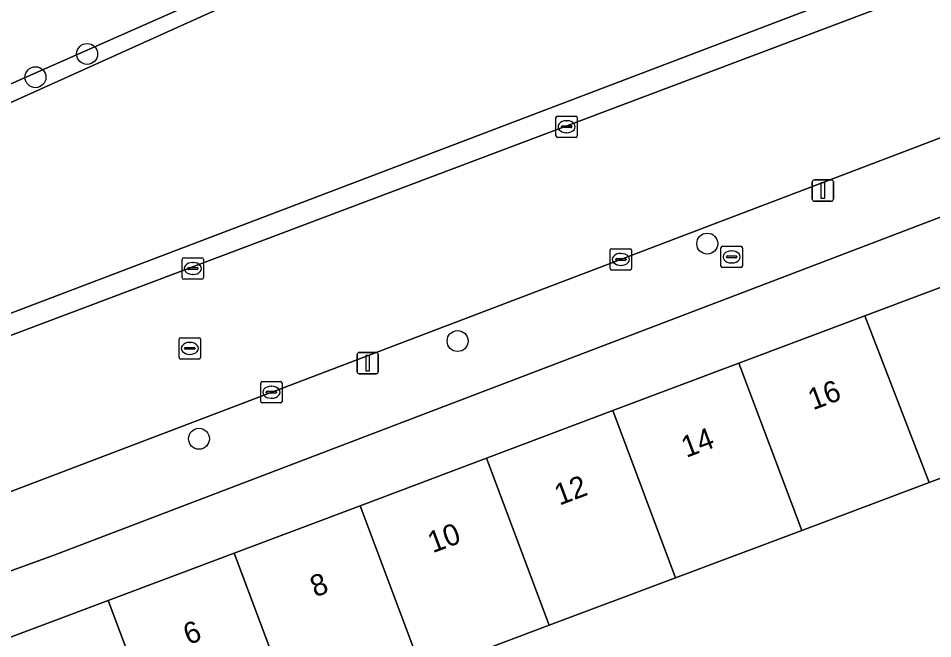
# Model space of a CAD drawing. Extents: x 161248 to 161848, y 384871 to 385383.
# Drawn here: x 161537.26 to 161580.03, y 385046.89 to 385075.88 of the extents above; entities that cross this region are included whole.
import ezdxf

# ---------------------------------------------------------------- set-up
doc = ezdxf.new("R2010")
doc.units = 0
for name, color, linetype in [('IMGEO_Boom', 7, 'Continuous'), ('IMGEO_Brandkraan', 7, 'Continuous'), ('IMGEO_Erf', 7, 'Continuous'), ('IMGEO_Groenvoorziening', 7, 'Continuous'), ('IMGEO_Kolk', 7, 'Continuous'), ('IMGEO_Lichtmast', 7, 'Continuous'), ('IMGEO_Pand', 7, 'Continuous'), ('IMGEO_Pand_nummerreeks', 7, 'Continuous'), ('IMGEO_Rijbaan_lokaal_open', 7, 'Continuous'), ('IMGEO_Rioolput', 7, 'Continuous'), ('IMGEO_Voetpad_halfverhard', 7, 'Continuous'), ('IMGEO_Voetpad_open', 7, 'Continuous')]:
    doc.layers.add(name, color=color, linetype=linetype)

msp = doc.modelspace()

# ---------------------------------------------------------------- linework, layer by layer
at = {"layer": 'IMGEO_Boom'}
for centre in [(161540.479, 385074.214), (161538.063, 385073.126), (161569.486, 385065.35), (161557.809, 385060.797), (161545.712, 385056.231)]:
    msp.add_circle(centre, 0.489, dxfattribs=at)
at = {"layer": 'IMGEO_Brandkraan'}
for p, q in [((161570.125, 385064.303), (161570.125, 385065.155)), ((161570.2, 385065.229), (161571.052, 385065.229)), ((161570.613, 385065.009), (161570.638, 385065.009)), ((161571.126, 385065.155), (161571.126, 385064.303)), ((161570.384, 385064.723), (161570.384, 385064.735)), ((161570.822, 385064.686), (161570.424, 385064.686)), ((161570.427, 385064.772), (161570.825, 385064.772)), ((161570.868, 385064.735), (161570.868, 385064.723)), ((161571.052, 385064.229), (161570.2, 385064.229)), ((161570.636, 385064.449), (161570.611, 385064.449))]:
    msp.add_line(p, q, dxfattribs=at)
for points in [[(161570.125, 385064.303), (161570.125, 385065.155)], [(161570.2, 385065.229), (161571.052, 385065.229)], [(161571.126, 385065.155), (161571.126, 385064.303)], [(161571.052, 385064.229), (161570.2, 385064.229)]]:
    msp.add_lwpolyline(points, dxfattribs=at)
for centre, radius, start, end in [((161570.202, 385065.153), 0.0765, 91.552, 178.448), ((161570.202, 385065.153), 0.0765, 91.552, 178.448), ((161571.05, 385065.153), 0.0765, 1.552, 88.448), ((161571.05, 385065.153), 0.0765, 1.552, 88.448), ((161570.424, 385064.732), 0.0403, 85.8775, 175.7526), ((161570.421, 385064.722), 0.0366, 178.938, 274.7102), ((161570.825, 385064.729), 0.043, 264.8664, 352.4533), ((161570.829, 385064.734), 0.0386, 1.7309, 96.639), ((161570.202, 385064.305), 0.0765, 181.552, 268.448), ((161570.202, 385064.305), 0.0765, 181.552, 268.448), ((161571.05, 385064.305), 0.0765, 271.552, 358.448), ((161571.05, 385064.305), 0.0765, 271.552, 358.448)]:
    msp.add_arc(centre, radius, start, end, dxfattribs=at)
for centre, major_axis, ratio, start_param, end_param in [((161570.612, 385064.729), (-0.387, 0.002), 0.722429, 4.712389, 7.853982), ((161570.637, 385064.729), (-0.39, 0.002), 0.717154, 1.570796, 4.712389)]:
    msp.add_ellipse(centre, major_axis=major_axis, ratio=ratio, start_param=start_param, end_param=end_param, dxfattribs=at)
at = {"layer": 'IMGEO_Erf'}
msp.add_lwpolyline([(161565.073, 385057.547), (161570.967, 385059.761), (161576.862, 385061.975), (161582.755, 385064.189), (161588.79, 385066.456), (161589.145, 385065.512), (161592.95, 385067.024), (161591.594, 385070.858), (161538.894, 385050.769), (161528.473, 385047.01), (161529.493, 385044.181), (161535.556, 385046.459), (161541.46, 385048.676), (161547.354, 385050.891), (161553.247, 385053.104), (161559.16, 385055.326)], close=True, dxfattribs=at)
msp.add_lwpolyline([(161584.899, 385044.98), (161583.845, 385047.786), (161588.289, 385049.455), (161592.924, 385051.196), (161593.978, 385048.391), (161594.068, 385048.384), (161594.788, 385056.581), (161592.778, 385055.838), (161592.992, 385055.269), (161586.963, 385053.005), (161585.689, 385056.378), (161579.872, 385054.193), (161573.901, 385051.95), (161568.007, 385049.736), (161562.095, 385047.515), (161556.182, 385045.294)], dxfattribs=at)
at = {"layer": 'IMGEO_Groenvoorziening'}
msp.add_lwpolyline([(161546.898, 385076.445), (161555.221, 385080.061), (161576.826, 385088.455), (161578.405, 385089.13), (161583.611, 385090.971), (161582.461, 385092.975), (161582.198, 385092.828), (161581.929, 385092.695), (161530.726, 385070.086), (161528.198, 385068.97), (161526.333, 385068.119), (161519.737, 385065.162), (161517.388, 385070.417), (161517.114, 385071.036), (161516.497, 385070.729), (161518.098, 385067.11), (161519.266, 385064.472), (161519.439, 385064.08)], close=True, dxfattribs=at)
msp.add_lwpolyline([(161589.28, 385082.44), (161583.611, 385090.971), (161578.405, 385089.13), (161576.826, 385088.455), (161555.221, 385080.061), (161546.898, 385076.445), (161519.439, 385064.08), (161519.074, 385063.916), (161512.396, 385060.909), (161515.187, 385054.666), (161520.946, 385056.425), (161531.74, 385060.145), (161584.888, 385080.338)], dxfattribs=at)
at = {"layer": 'IMGEO_Kolk'}
for p, q in [((161562.405, 385070.387), (161562.405, 385071.239)), ((161562.48, 385071.313), (161563.332, 385071.313)), ((161562.893, 385071.093), (161562.918, 385071.093)), ((161563.406, 385071.239), (161563.406, 385070.387)), ((161562.664, 385070.807), (161562.664, 385070.819)), ((161563.102, 385070.77), (161562.704, 385070.77)), ((161562.707, 385070.856), (161563.105, 385070.856)), ((161562.916, 385070.533), (161562.891, 385070.533)), ((161563.148, 385070.819), (161563.148, 385070.807)), ((161563.332, 385070.313), (161562.48, 385070.313)), ((161564.944, 385064.185), (161564.944, 385065.037)), ((161565.019, 385065.111), (161565.871, 385065.111)), ((161565.945, 385065.037), (161565.945, 385064.185)), ((161544.924, 385063.762), (161544.924, 385064.614)), ((161544.999, 385064.688), (161545.851, 385064.688)), ((161545.925, 385064.614), (161545.925, 385063.762)), ((161565.203, 385064.605), (161565.203, 385064.617)), ((161565.641, 385064.568), (161565.243, 385064.568)), ((161565.246, 385064.654), (161565.644, 385064.654)), ((161565.432, 385064.891), (161565.457, 385064.891)), ((161565.687, 385064.617), (161565.687, 385064.605)), ((161545.183, 385064.182), (161545.183, 385064.194)), ((161545.621, 385064.145), (161545.223, 385064.145)), ((161545.226, 385064.231), (161545.624, 385064.231)), ((161545.412, 385064.468), (161545.437, 385064.468)), ((161545.667, 385064.194), (161545.667, 385064.182)), ((161565.871, 385064.111), (161565.019, 385064.111)), ((161565.455, 385064.331), (161565.43, 385064.331)), ((161545.851, 385063.688), (161544.999, 385063.688)), ((161545.435, 385063.908), (161545.41, 385063.908)), ((161548.6, 385057.979), (161548.6, 385058.831)), ((161548.675, 385058.905), (161549.527, 385058.905)), ((161549.088, 385058.685), (161549.113, 385058.685)), ((161549.601, 385058.831), (161549.601, 385057.979)), ((161548.859, 385058.399), (161548.859, 385058.411)), ((161549.297, 385058.362), (161548.899, 385058.362)), ((161548.902, 385058.448), (161549.3, 385058.448)), ((161549.111, 385058.125), (161549.086, 385058.125)), ((161549.343, 385058.411), (161549.343, 385058.399)), ((161549.527, 385057.905), (161548.675, 385057.905))]:
    msp.add_line(p, q, dxfattribs=at)
for points in [[(161562.405, 385070.387), (161562.405, 385071.239)], [(161562.48, 385071.313), (161563.332, 385071.313)], [(161563.406, 385071.239), (161563.406, 385070.387)], [(161563.332, 385070.313), (161562.48, 385070.313)], [(161564.944, 385064.185), (161564.944, 385065.037)], [(161565.019, 385065.111), (161565.871, 385065.111)], [(161565.945, 385065.037), (161565.945, 385064.185)], [(161544.924, 385063.762), (161544.924, 385064.614)], [(161544.999, 385064.688), (161545.851, 385064.688)], [(161545.925, 385064.614), (161545.925, 385063.762)], [(161565.871, 385064.111), (161565.019, 385064.111)], [(161545.851, 385063.688), (161544.999, 385063.688)], [(161548.6, 385057.979), (161548.6, 385058.831)], [(161548.675, 385058.905), (161549.527, 385058.905)], [(161549.601, 385058.831), (161549.601, 385057.979)], [(161549.527, 385057.905), (161548.675, 385057.905)]]:
    msp.add_lwpolyline(points, dxfattribs=at)
for centre, radius, start, end in [((161562.482, 385071.237), 0.0765, 91.552, 178.448), ((161562.482, 385071.237), 0.0765, 91.552, 178.448), ((161563.33, 385071.237), 0.0765, 1.552, 88.448), ((161563.33, 385071.237), 0.0765, 1.552, 88.448), ((161562.704, 385070.816), 0.0403, 85.8775, 175.7526), ((161562.701, 385070.806), 0.0366, 178.938, 274.7102), ((161563.105, 385070.813), 0.043, 264.8664, 352.4533), ((161563.109, 385070.818), 0.0386, 1.7309, 96.639), ((161562.482, 385070.389), 0.0765, 181.552, 268.448), ((161562.482, 385070.389), 0.0765, 181.552, 268.448), ((161563.33, 385070.389), 0.0765, 271.552, 358.448), ((161563.33, 385070.389), 0.0765, 271.552, 358.448), ((161565.021, 385065.035), 0.0765, 91.552, 178.448), ((161565.021, 385065.035), 0.0765, 91.552, 178.448), ((161565.869, 385065.035), 0.0765, 1.552, 88.448), ((161565.869, 385065.035), 0.0765, 1.552, 88.448), ((161545.001, 385064.612), 0.0765, 91.552, 178.448), ((161545.001, 385064.612), 0.0765, 91.552, 178.448), ((161545.849, 385064.612), 0.0765, 1.552, 88.448), ((161545.849, 385064.612), 0.0765, 1.552, 88.448), ((161565.243, 385064.614), 0.0403, 85.8775, 175.7526), ((161565.24, 385064.604), 0.0366, 178.938, 274.7102), ((161565.644, 385064.611), 0.043, 264.8664, 352.4533), ((161565.648, 385064.616), 0.0386, 1.7309, 96.639), ((161545.223, 385064.191), 0.0403, 85.8775, 175.7526), ((161545.22, 385064.181), 0.0366, 178.938, 274.7102), ((161545.624, 385064.188), 0.043, 264.8664, 352.4533), ((161545.628, 385064.193), 0.0386, 1.7309, 96.639), ((161565.021, 385064.187), 0.0765, 181.552, 268.448), ((161565.021, 385064.187), 0.0765, 181.552, 268.448), ((161565.869, 385064.187), 0.0765, 271.552, 358.448), ((161565.869, 385064.187), 0.0765, 271.552, 358.448), ((161545.001, 385063.764), 0.0765, 181.552, 268.448), ((161545.001, 385063.764), 0.0765, 181.552, 268.448), ((161545.849, 385063.764), 0.0765, 271.552, 358.448), ((161545.849, 385063.764), 0.0765, 271.552, 358.448), ((161548.677, 385058.829), 0.0765, 91.552, 178.448), ((161548.677, 385058.829), 0.0765, 91.552, 178.448), ((161549.525, 385058.829), 0.0765, 1.552, 88.448), ((161549.525, 385058.829), 0.0765, 1.552, 88.448), ((161548.899, 385058.408), 0.0403, 85.8775, 175.7526), ((161548.896, 385058.398), 0.0366, 178.938, 274.7102), ((161549.3, 385058.405), 0.043, 264.8664, 352.4533), ((161549.304, 385058.41), 0.0386, 1.7309, 96.639), ((161548.677, 385057.981), 0.0765, 181.552, 268.448), ((161548.677, 385057.981), 0.0765, 181.552, 268.448), ((161549.525, 385057.981), 0.0765, 271.552, 358.448), ((161549.525, 385057.981), 0.0765, 271.552, 358.448)]:
    msp.add_arc(centre, radius, start, end, dxfattribs=at)
for centre, major_axis, ratio, start_param, end_param in [((161562.892, 385070.813), (-0.387, 0.002), 0.722429, 4.712389, 7.853982), ((161562.917, 385070.813), (-0.39, 0.002), 0.717154, 1.570796, 4.712389), ((161565.431, 385064.611), (-0.387, 0.002), 0.722429, 4.712389, 7.853982), ((161565.456, 385064.611), (-0.39, 0.002), 0.717154, 1.570796, 4.712389), ((161545.411, 385064.188), (-0.387, 0.002), 0.722429, 4.712389, 7.853982), ((161545.436, 385064.188), (-0.39, 0.002), 0.717154, 1.570796, 4.712389), ((161549.087, 385058.405), (-0.387, 0.002), 0.722429, 4.712389, 7.853982), ((161549.112, 385058.405), (-0.39, 0.002), 0.717154, 1.570796, 4.712389)]:
    msp.add_ellipse(centre, major_axis=major_axis, ratio=ratio, start_param=start_param, end_param=end_param, dxfattribs=at)
at = {"layer": 'IMGEO_Lichtmast'}
for p, q in [((161574.495, 385068.33), (161575.285, 385068.33)), ((161575.285, 385068.33), (161574.495, 385068.33)), ((161574.395, 385067.43), (161574.395, 385068.23)), ((161574.395, 385068.23), (161574.395, 385067.43)), ((161575.385, 385068.23), (161575.385, 385067.43)), ((161575.385, 385067.43), (161575.385, 385068.23)), ((161575.285, 385067.33), (161574.495, 385067.33)), ((161574.495, 385067.33), (161575.285, 385067.33)), ((161553.208, 385060.266), (161553.998, 385060.266)), ((161553.998, 385060.266), (161553.208, 385060.266)), ((161553.108, 385059.366), (161553.108, 385060.166)), ((161553.108, 385060.166), (161553.108, 385059.366)), ((161554.098, 385060.166), (161554.098, 385059.366)), ((161554.098, 385059.366), (161554.098, 385060.166)), ((161553.998, 385059.266), (161553.208, 385059.266)), ((161553.208, 385059.266), (161553.998, 385059.266))]:
    msp.add_line(p, q, dxfattribs=at)
for points in [[(161574.815, 385068.205), (161574.965, 385068.205), (161574.965, 385067.455), (161574.815, 385067.455), (161574.815, 385068.205)], [(161553.528, 385060.141), (161553.678, 385060.141), (161553.678, 385059.391), (161553.528, 385059.391), (161553.528, 385060.141)]]:
    msp.add_lwpolyline(points, dxfattribs=at)
for centre, start, end in [((161574.495, 385068.23), 90, 180), ((161574.495, 385068.23), 90, 180), ((161575.285, 385068.23), 0, 90), ((161575.285, 385068.23), 360, 90), ((161574.495, 385067.43), 180, 270), ((161574.495, 385067.43), 180, 270), ((161575.285, 385067.43), 270, 0), ((161575.285, 385067.43), 270, 0), ((161553.208, 385060.166), 90, 180), ((161553.208, 385060.166), 90, 180), ((161553.998, 385060.166), 0, 90), ((161553.998, 385060.166), 360, 90), ((161553.208, 385059.366), 180, 270), ((161553.208, 385059.366), 180, 270), ((161553.998, 385059.366), 270, 0), ((161553.998, 385059.366), 270, 0)]:
    msp.add_arc(centre, 0.1, start, end, dxfattribs=at)
at = {"layer": 'IMGEO_Pand'}
for points in [[(161582.755, 385064.189), (161576.862, 385061.975), (161579.872, 385054.193), (161585.689, 385056.378)], [(161573.901, 385051.95), (161579.872, 385054.193), (161576.862, 385061.975), (161570.967, 385059.761)], [(161568.007, 385049.736), (161573.901, 385051.95), (161570.967, 385059.761), (161565.073, 385057.547)], [(161565.073, 385057.547), (161559.16, 385055.326), (161562.095, 385047.515), (161568.007, 385049.736)], [(161559.16, 385055.326), (161553.247, 385053.104), (161556.182, 385045.294), (161562.095, 385047.515)], [(161550.288, 385043.079), (161556.182, 385045.294), (161553.247, 385053.104), (161547.354, 385050.891)], [(161544.394, 385040.865), (161550.288, 385043.079), (161547.354, 385050.891), (161541.46, 385048.676)], [(161541.46, 385048.676), (161535.556, 385046.459), (161538.491, 385038.648), (161544.394, 385040.865)]]:
    msp.add_lwpolyline(points, close=True, dxfattribs=at)
at = {"layer": 'IMGEO_Rijbaan_lokaal_open'}
msp.add_lwpolyline([(161586.502, 385079.759), (161585.906, 385079.534), (161529.392, 385058.239), (161520.264, 385055.172), (161506.266, 385050.857), (161508.319, 385044.433), (161516.58, 385046.703), (161521.95, 385048.386), (161525.446, 385049.549), (161527.874, 385050.388), (161535.71, 385053.309), (161590.259, 385074.054)], dxfattribs=at)
at = {"layer": 'IMGEO_Rioolput'}
for p, q in [((161544.783, 385060.027), (161544.783, 385060.879)), ((161544.858, 385060.953), (161545.71, 385060.953)), ((161545.271, 385060.733), (161545.296, 385060.733)), ((161545.784, 385060.879), (161545.784, 385060.027)), ((161545.042, 385060.447), (161545.042, 385060.459)), ((161545.48, 385060.41), (161545.082, 385060.41)), ((161545.085, 385060.496), (161545.483, 385060.496)), ((161545.526, 385060.459), (161545.526, 385060.447)), ((161545.71, 385059.953), (161544.858, 385059.953)), ((161545.294, 385060.173), (161545.269, 385060.173))]:
    msp.add_line(p, q, dxfattribs=at)
for points in [[(161544.783, 385060.027), (161544.783, 385060.879)], [(161544.858, 385060.953), (161545.71, 385060.953)], [(161545.784, 385060.879), (161545.784, 385060.027)], [(161545.71, 385059.953), (161544.858, 385059.953)]]:
    msp.add_lwpolyline(points, dxfattribs=at)
for centre, radius, start, end in [((161544.86, 385060.877), 0.0765, 91.552, 178.448), ((161544.86, 385060.877), 0.0765, 91.552, 178.448), ((161545.708, 385060.877), 0.0765, 1.552, 88.448), ((161545.708, 385060.877), 0.0765, 1.552, 88.448), ((161545.082, 385060.456), 0.0403, 85.8775, 175.7526), ((161545.079, 385060.446), 0.0366, 178.938, 274.7102), ((161545.483, 385060.453), 0.043, 264.8664, 352.4533), ((161545.487, 385060.458), 0.0386, 1.7309, 96.639), ((161544.86, 385060.029), 0.0765, 181.552, 268.448), ((161544.86, 385060.029), 0.0765, 181.552, 268.448), ((161545.708, 385060.029), 0.0765, 271.552, 358.448), ((161545.708, 385060.029), 0.0765, 271.552, 358.448)]:
    msp.add_arc(centre, radius, start, end, dxfattribs=at)
for centre, major_axis, ratio, start_param, end_param in [((161545.27, 385060.453), (-0.387, 0.002), 0.722429, 4.712389, 7.853982), ((161545.295, 385060.453), (-0.39, 0.002), 0.717154, 1.570796, 4.712389)]:
    msp.add_ellipse(centre, major_axis=major_axis, ratio=ratio, start_param=start_param, end_param=end_param, dxfattribs=at)
at = {"layer": 'IMGEO_Voetpad_halfverhard'}
msp.add_lwpolyline([(161530.726, 385070.086), (161581.929, 385092.695)], dxfattribs=at)
at = {"layer": 'IMGEO_Voetpad_open'}
for points in [[(161527.147, 385046.532), (161528.473, 385047.01), (161538.894, 385050.769), (161591.594, 385070.858), (161592.95, 385067.024), (161595.155, 385061.233), (161594.788, 385056.581), (161594.068, 385048.384), (161593.863, 385046.965), (161595.047, 385046.848), (161596.272, 385062.029), (161592.706, 385071.279), (161596.479, 385072.714), (161597.661, 385073.166), (161598.554, 385070.923), (161599.306, 385070.624), (161609.012, 385095.368)], [(161584.888, 385080.338), (161531.74, 385060.145), (161520.946, 385056.425), (161515.187, 385054.666), (161505.845, 385051.813)], [(161506.266, 385050.857), (161520.264, 385055.172), (161529.392, 385058.239), (161585.906, 385079.534), (161586.502, 385079.759)], [(161590.259, 385074.054), (161535.71, 385053.309), (161527.874, 385050.388), (161525.446, 385049.549), (161525.603, 385049.075), (161522.107, 385047.913), (161521.95, 385048.386), (161516.58, 385046.703)]]:
    msp.add_lwpolyline(points, dxfattribs=at)

# ---------------------------------------------------------------- texts
at = {"layer": 'IMGEO_Pand_nummerreeks'}
for s, p in [('16', (161574.432, 385057.558)), ('14', (161568.502, 385055.331)), ('12', (161562.569, 385053.102)), ('10', (161556.644, 385050.877)), ('8', (161551.146, 385048.811)), ('6', (161545.213, 385046.583))]:
    msp.add_text(s, height=1, rotation=20.5888, dxfattribs=at).set_placement(p)

doc.saveas('drawing.dxf')
